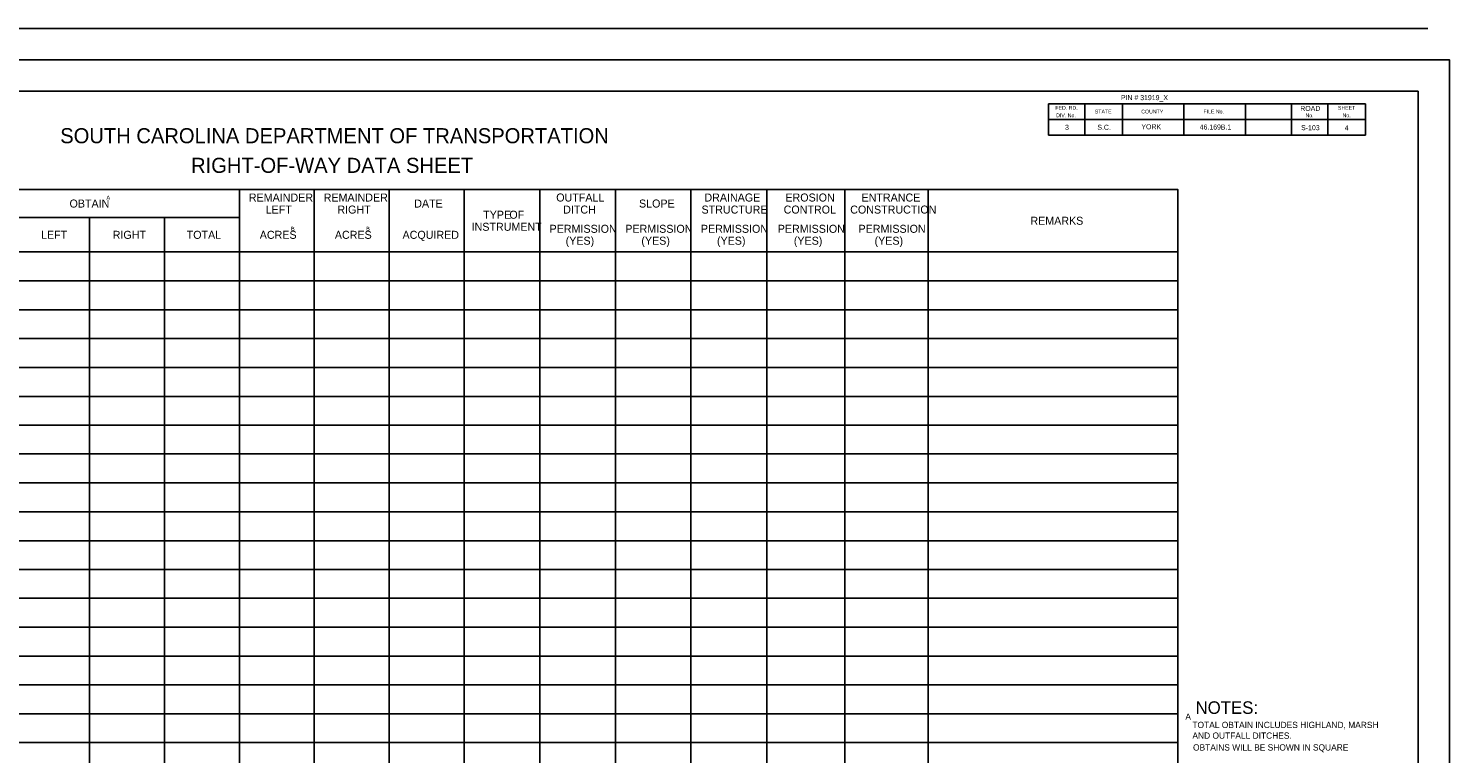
# Model space of a CAD drawing. Extents: x -19 to 1777, y -25 to 1125.
# Drawn here: x 646 to 1777, y 548 to 1125 of the extents above; entities that cross this region are included whole.
import ezdxf

# ---------------------------------------------------------------- set-up
doc = ezdxf.new("R2010")
doc.units = 0
for name, color, linetype in [('RD_SHT_Bndy', 7, 'Continuous'), ('RD_SHT_Iplotshp', 7, 'Continuous'), ('RD_SHT_MjGrid', 7, 'Continuous'), ('RD_SHT_Snap', 7, 'Continuous'), ('RD_SHT_TX', 7, 'Continuous'), ('RD_TX_RW', 7, 'Continuous')]:
    doc.layers.add(name, color=color, linetype=linetype)

msp = doc.modelspace()

# ---------------------------------------------------------------- linework, layer by layer
at = {"layer": 'RD_SHT_Bndy'}
for p, q in [((0, 1125), (1760, 1125)), ((0, 1100), (1760, 1100)), ((1752.4, 1075), (77.4, 1075)), ((1457.9, 1065), (1710.4, 1065)), ((1457.9, 1065), (1457.9, 1052.5)), ((1486.9, 1065), (1486.9, 1052.5)), ((1516.9, 1065), (1516.9, 1052.5)), ((1565.9, 1065), (1565.9, 1052.5)), ((1614.9, 1065), (1614.9, 1052.5)), ((1651.4, 1065), (1651.4, 1052.5)), ((1680.4, 1065), (1680.4, 1052.5)), ((1710.4, 1065), (1710.4, 1052.5)), ((1752.4, 25), (1752.4, 1075)), ((1457.9, 1052.5), (1710.4, 1052.5)), ((1457.9, 1052.5), (1457.9, 1040)), ((1486.9, 1052.5), (1486.9, 1049.4)), ((1486.9, 1049.4), (1486.9, 1040)), ((1516.9, 1052.5), (1516.9, 1040)), ((1565.9, 1052.5), (1565.9, 1040)), ((1614.9, 1052.5), (1614.9, 1040)), ((1651.4, 1052.5), (1651.4, 1040)), ((1680.4, 1052.5), (1680.4, 1040)), ((1710.4, 1052.5), (1710.4, 1040)), ((1457.9, 1040), (1710.4, 1040))]:
    msp.add_line(p, q, dxfattribs=at)
msp.add_lwpolyline([(218, 142.7), (1560.9, 142.7), (1560.9, 996.8), (218, 996.8)], close=True, dxfattribs=at)
at = {"layer": 'RD_SHT_Iplotshp'}
msp.add_lwpolyline([(-18.6, 1100), (1777.4, 1100), (1777.4, 0), (-18.6, 0)], close=True, dxfattribs=at)
at = {"layer": 'RD_SHT_MjGrid'}
for p, q in [((218, 996.8), (1560.9, 996.8)), ((813.7, 142.7), (813.7, 996.8)), ((873.3, 142.7), (873.3, 996.8)), ((932.9, 142.7), (932.9, 996.8)), ((992.6, 142.7), (992.6, 996.8)), ((1052.8, 142.7), (1052.8, 996.8)), ((1113.1, 142.7), (1113.1, 996.8)), ((1173.3, 142.7), (1173.3, 996.8)), ((1233.6, 142.7), (1233.6, 996.8)), ((1295.7, 142.7), (1295.7, 996.8)), ((1362.1, 142.7), (1362.1, 996.8)), ((1560.9, 142.7), (1560.9, 996.8)), ((575.2, 974.4), (813.7, 974.4)), ((694.4, 142.7), (694.4, 974.4)), ((754, 142.7), (754, 974.4)), ((218, 947.1), (1560.9, 947.1)), ((992.6, 947.1), (1362.1, 947.1)), ((1362.1, 947.1), (1560.9, 947.1)), ((218, 924.1), (1560.9, 924.1)), ((218, 901.1), (1560.9, 901.1)), ((218, 878.1), (1560.9, 878.1)), ((694.4, 878.1), (1560.9, 878.1)), ((218, 855.1), (1560.9, 855.1)), ((218, 832.1), (1560.9, 832.1)), ((218, 809.2), (1560.9, 809.2)), ((218, 786.2), (1560.9, 786.2)), ((218, 763.2), (1560.9, 763.2)), ((218, 740.2), (1560.9, 740.2)), ((218, 717.2), (1560.9, 717.2)), ((218, 694.3), (1560.9, 694.3)), ((218, 671.3), (1560.9, 671.3)), ((218, 648.3), (1560.9, 648.3)), ((218, 625.3), (1560.9, 625.3)), ((218, 602.3), (1560.9, 602.3)), ((218, 579.3), (1560.9, 579.3)), ((218, 556.4), (1560.9, 556.4))]:
    msp.add_line(p, q, dxfattribs=at)
at = {"layer": 'RD_SHT_Snap'}
msp.add_line((1777.4, 0), (1777.4, 1100), dxfattribs=at)

# ---------------------------------------------------------------- texts
at = {"layer": 'RD_SHT_TX'}
for s, height, p in [('PIN # 31919_X', 4, (1515.7, 1067.9)), ('FED. RD.', 3, (1463.5, 1060.3)), ('DIV. No.', 3, (1464.1, 1054.3)), ('STATE', 3, (1494.9, 1057.3)), ('COUNTY', 3, (1531.9, 1057.3)), ('FILE No.', 3, (1581.4, 1057.3)), ('ROAD', 4, (1658.5, 1059.3)), ('No.', 3, (1662.7, 1054.3)), ('SHEET', 3, (1688.5, 1060.3)), ('No.', 3, (1692.2, 1054.3)), ('SOUTH CAROLINA DEPARTMENT OF TRANSPORTATION', 12, (671, 1033.6)), ('3', 4, (1471.2, 1044.3)), ('S.C.', 4, (1496.9, 1044.3)), ('YORK', 4, (1532, 1044.7)), ('46.169B.1', 4, (1578.4, 1044.5)), ('S-103', 4, (1659.2, 1044)), ('4', 4, (1693.9, 1043.8)), ('RIGHT-OF-WAY DATA SHEET', 12, (775.2, 1010)), ('NOTES:', 10, (1575.1, 579.3)), ('A', 5, (1567, 574.6)), ('TOTAL OBTAIN INCLUDES HIGHLAND, MARSH', 5, (1572.6, 568)), ('AND OUTFALL DITCHES. ', 5, (1572.6, 559.5)), ('OBTAINS WILL BE SHOWN IN SQUARE', 5, (1573.1, 550.1))]:
    msp.add_text(s, height=height, dxfattribs=at).set_placement(p)
at = {"layer": 'RD_TX_RW'}
for s, height, p in [('OBTAIN', 6.37, (678.4, 982.4)), ('A', 3.19, (707.8, 988.8)), ('REMAINDER', 6.37, (821.2, 987.2)), ('REMAINDER', 6.37, (880.8, 987.2)), ('DATE', 6.37, (952.9, 982.4)), ('OUTFALL', 6.37, (1066, 987.2)), ('SLOPE', 6.37, (1131.9, 982.4)), ('DRAINAGE', 6.37, (1184, 987.2)), ('EROSION', 6.37, (1248.5, 987.2)), ('ENTRANCE', 6.37, (1309.1, 987.2)), ('LEFT', 6.37, (834.6, 977.6)), ('RIGHT', 6.37, (891.7, 977.6)), ('TYPE', 6.37, (1007.8, 973.5)), (' OF', 6.37, (1026.3, 973.5)), ('DITCH', 6.37, (1071.5, 977.6)), ('STRUCTURE', 6.37, (1181.7, 977.6)), ('CONTROL', 6.37, (1247.1, 977.6)), ('CONSTRUCTION', 6.371, (1300.1, 977.6)), ('REMARKS', 6.37, (1443.6, 968.7)), ('LEFT', 6.37, (655.7, 957.5)), ('RIGHT', 6.37, (712.8, 957.5)), ('TOTAL', 6.37, (771.7, 957.5)), ('ACRES', 6.37, (829.9, 957.5)), ('B', 3.19, (854.8, 963.9)), ('ACRES', 6.37, (889.7, 957.5)), (' B', 3.19, (913.4, 963.9)), ('ACQUIRED', 6.37, (943.6, 957.5)), ('INSTRUMENT', 6.37, (998.6, 963.9)), ('PERMISSION', 6.37, (1060.7, 962.3)), ('PERMISSION', 6.37, (1121, 962.3)), ('PERMISSION', 6.37, (1181.2, 962.3)), ('PERMISSION', 6.37, (1242.4, 962.3)), ('PERMISSION', 6.37, (1306.7, 962.3)), ('(YES)', 6.37, (1073.5, 952.8)), ('(YES)', 6.37, (1133.8, 952.8)), ('(YES)', 6.37, (1194, 952.8)), ('(YES)', 6.37, (1255.2, 952.8)), ('(YES)', 6.37, (1319.5, 952.8))]:
    msp.add_text(s, height=height, dxfattribs=at).set_placement(p)

doc.saveas('drawing.dxf')
